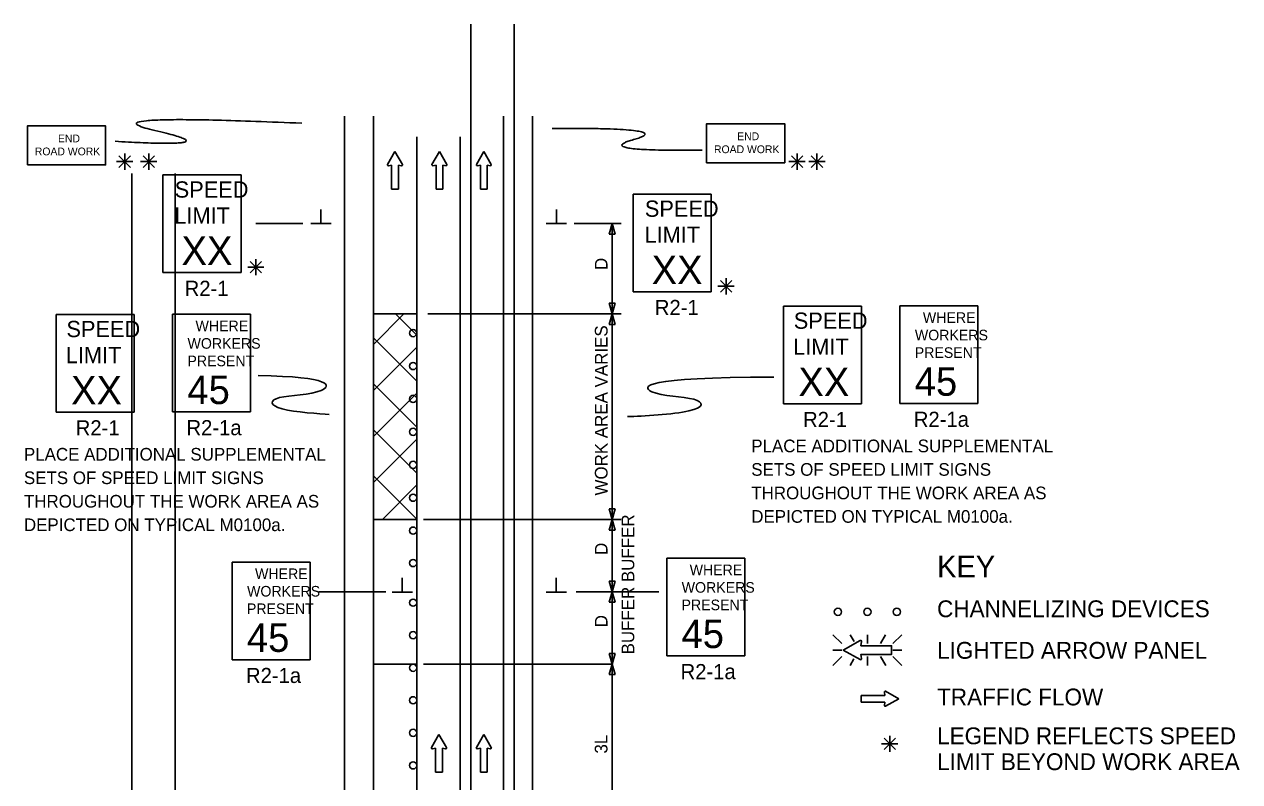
# Model space of a CAD drawing. Extents: x 16576 to 19504, y 5728 to 6974.
# Drawn here: x 16734 to 17406, y 6555 to 6974 of the extents above; entities that cross this region are included whole.
import ezdxf

# ---------------------------------------------------------------- set-up
doc = ezdxf.new("R2010")
doc.units = 0
for name, color, linetype in [('ALI_LEGAL_EX', 7, 'Continuous'), ('MT_SCRATCH_LEVEL_E', 7, 'Continuous'), ('PAVT_EDGE_EX', 7, 'Continuous'), ('TRAFFIC_SIGNS_PR', 7, 'Continuous'), ('TYPICAL_TEXT_DIMEN_EX', 7, 'Continuous'), ('TYPICAL_TEXT_DIMEN_PR', 7, 'Continuous')]:
    doc.layers.add(name, color=color, linetype=linetype)

msp = doc.modelspace()

# ---------------------------------------------------------------- linework, layer by layer
at = {"layer": 'ALI_LEGAL_EX'}
for p, q in [((16980.68, 6974.12), (16980.68, 6155.98)), ((17004.68, 6974.12), (17004.68, 6155.98)), ((16950.77, 6911.88), (16950.77, 6082.69)), ((16974.77, 6911.88), (16974.77, 6082.69)), ((16793.2, 6891.57), (16793.2, 6027.66)), ((16817.2, 6891.57), (16817.2, 6027.66))]:
    msp.add_line(p, q, dxfattribs=at)
for points in [[(17004.68, 6949.12), (17004.68, 6974.12)], [(16950.77, 6911.88), (16950.77, 6886.88)], [(16974.77, 6911.88), (16974.77, 6886.88)], [(16950.77, 6811.88), (16950.77, 6786.88)], [(16974.77, 6811.88), (16974.77, 6786.88)], [(16950.77, 6711.88), (16950.77, 6686.88)], [(16974.77, 6711.88), (16974.77, 6686.88)], [(16950.77, 6611.88), (16950.77, 6586.88)], [(16974.77, 6611.88), (16974.77, 6586.88)]]:
    msp.add_lwpolyline(points, dxfattribs=at)
at = {"layer": 'MT_SCRATCH_LEVEL_E'}
for p, q in [((16938.74, 6903.85), (16934.63, 6896.61)), ((16942.89, 6896.61), (16938.74, 6903.85)), ((16963.3, 6903.85), (16959.19, 6896.61)), ((16967.44, 6896.61), (16963.3, 6903.85)), ((16987.86, 6903.85), (16983.75, 6896.61)), ((16992, 6896.61), (16987.86, 6903.85)), ((16935.11, 6895.92), (16936.89, 6896.24)), ((16936.89, 6896.24), (16936.89, 6882.98)), ((16940.63, 6882.98), (16940.63, 6896.24)), ((16940.63, 6896.24), (16942.41, 6895.92)), ((16959.67, 6895.92), (16961.45, 6896.24)), ((16961.45, 6896.24), (16961.45, 6882.98)), ((16965.19, 6882.98), (16965.19, 6896.24)), ((16965.19, 6896.24), (16966.97, 6895.92)), ((16984.23, 6895.92), (16986.01, 6896.24)), ((16986.01, 6896.24), (16986.01, 6882.98)), ((16989.75, 6882.98), (16989.75, 6896.24)), ((16989.75, 6896.24), (16991.53, 6895.92)), ((16936.89, 6882.98), (16940.63, 6882.98)), ((16961.45, 6882.98), (16965.19, 6882.98)), ((16986.01, 6882.98), (16989.75, 6882.98)), ((17209.76, 6602.9), (17196.5, 6602.9)), ((17196.5, 6602.9), (17196.5, 6599.15)), ((17209.44, 6604.67), (17209.76, 6602.9)), ((17217.37, 6601.04), (17210.13, 6605.16)), ((17196.5, 6599.15), (17209.76, 6599.15)), ((17209.76, 6599.15), (17209.44, 6597.38)), ((17210.13, 6596.9), (17217.37, 6601.04)), ((16963.08, 6581.24), (16958.97, 6574)), ((16967.23, 6574), (16963.08, 6581.24)), ((16987.86, 6581.26), (16983.75, 6574.02)), ((16992, 6574.02), (16987.86, 6581.26)), ((16959.45, 6573.32), (16961.23, 6573.63)), ((16961.23, 6573.63), (16961.23, 6560.38)), ((16964.97, 6560.38), (16964.97, 6573.63)), ((16964.97, 6573.63), (16966.75, 6573.32)), ((16984.23, 6573.33), (16986.01, 6573.65)), ((16986.01, 6573.65), (16986.01, 6560.39)), ((16989.75, 6560.39), (16989.75, 6573.65)), ((16989.75, 6573.65), (16991.53, 6573.33)), ((16961.23, 6560.38), (16964.97, 6560.38)), ((16986.01, 6560.39), (16989.75, 6560.39))]:
    msp.add_line(p, q, dxfattribs=at)
for centre, start, end in [((16935.04, 6896.38), 150.42484, 279.96381), ((16942.48, 6896.38), 260.03619, 29.77312), ((16959.59, 6896.38), 150.42484, 279.96381), ((16967.04, 6896.38), 260.03619, 29.77312), ((16984.15, 6896.38), 150.42484, 279.96381), ((16991.59, 6896.38), 260.03619, 29.77312), ((17209.9, 6604.75), 60.42484, 189.96381), ((17209.9, 6597.31), 170.03619, 299.77312), ((16959.38, 6573.78), 150.42484, 279.96381), ((16966.82, 6573.78), 260.03619, 29.77312), ((16984.15, 6573.79), 150.42484, 279.96381), ((16991.59, 6573.79), 260.03619, 29.77312)]:
    msp.add_arc(centre, 0.463, start, end, dxfattribs=at)
at = {"layer": 'PAVT_EDGE_EX'}
for p, q in [((16910.77, 6923.28), (16910.77, 5986.88)), ((16926.77, 6923.28), (16926.77, 5986.88)), ((16998.77, 6923.28), (16998.77, 5986.88)), ((17014.77, 6923.28), (17014.77, 5986.88)), ((16926.77, 6813.97), (16950.77, 6813.97)), ((16926.77, 6797.07), (16943.67, 6813.97)), ((16950.86, 6813.97), (16926.86, 6813.97)), ((16950.77, 6802.15), (16938.96, 6813.97)), ((16950.77, 6776.7), (16926.77, 6800.7)), ((16926.77, 6771.61), (16950.77, 6795.61)), ((16950.77, 6751.24), (16926.77, 6775.24)), ((16926.77, 6746.16), (16950.77, 6770.16)), ((16950.77, 6725.79), (16926.77, 6749.79)), ((16926.77, 6720.7), (16950.77, 6744.7)), ((16950.77, 6700.33), (16926.77, 6724.33)), ((16931.77, 6700.24), (16950.86, 6719.34))]:
    msp.add_line(p, q, dxfattribs=at)
msp.add_lwpolyline([(16950.86, 6700.24), (16926.77, 6700.24), (16926.77, 6620.24), (16950.86, 6620.24)], close=True, dxfattribs=at)
at = {"layer": 'TRAFFIC_SIGNS_PR'}
for p, q in [((16810.4, 6890.77), (16853.6, 6890.77)), ((16810.4, 6836.77), (16810.4, 6890.77)), ((16853.6, 6836.77), (16853.6, 6890.77)), ((17070.45, 6880.17), (17113.65, 6880.17)), ((17070.45, 6826.17), (17070.45, 6880.17)), ((17113.65, 6826.17), (17113.65, 6880.17)), ((16810.4, 6836.77), (16853.6, 6836.77)), ((17070.45, 6826.17), (17113.65, 6826.17)), ((17153.65, 6818.22), (17196.85, 6818.22)), ((17153.65, 6764.22), (17153.65, 6818.22)), ((17196.85, 6764.22), (17196.85, 6818.22)), ((17218, 6818.32), (17261.2, 6818.32)), ((17218, 6764.32), (17218, 6818.32)), ((17261.2, 6764.32), (17261.2, 6818.32)), ((16751.34, 6813.6), (16794.54, 6813.6)), ((16751.34, 6759.6), (16751.34, 6813.6)), ((16794.54, 6759.6), (16794.54, 6813.6)), ((16815.69, 6813.7), (16858.89, 6813.7)), ((16815.69, 6759.7), (16815.69, 6813.7)), ((16858.89, 6759.7), (16858.89, 6813.7)), ((17153.65, 6764.22), (17196.85, 6764.22)), ((17218, 6764.32), (17261.2, 6764.32)), ((16751.34, 6759.6), (16794.54, 6759.6)), ((16815.69, 6759.7), (16858.89, 6759.7)), ((16848.61, 6676.62), (16891.81, 6676.62)), ((16848.61, 6622.62), (16848.61, 6676.62)), ((16891.81, 6622.62), (16891.81, 6676.62)), ((17089.01, 6678.74), (17132.21, 6678.74)), ((17089.01, 6624.74), (17089.01, 6678.74)), ((17132.21, 6624.74), (17132.21, 6678.74)), ((17180.95, 6636.47), (17185.88, 6631.54)), ((17192.71, 6632.65), (17190.51, 6636.47)), ((17200.03, 6631.54), (17200.03, 6636.47)), ((17207.27, 6631.54), (17210.12, 6636.47)), ((17214.18, 6631.54), (17219.12, 6636.48)), ((16848.61, 6622.62), (16891.81, 6622.62)), ((17089.01, 6624.74), (17132.21, 6624.74)), ((17185.88, 6627.98), (17180.95, 6627.98)), ((17180.95, 6619.5), (17185.88, 6624.43)), ((17190.46, 6619.49), (17192.57, 6623.16)), ((17200.03, 6624.43), (17200.03, 6619.49)), ((17210.16, 6619.49), (17207.31, 6624.43)), ((17214.18, 6627.98), (17219.12, 6627.98)), ((17214.18, 6624.43), (17219.12, 6619.49))]:
    msp.add_line(p, q, dxfattribs=at)
for points in [[(16735.46, 6896.3), (16778.66, 6896.3), (16778.66, 6917.9), (16735.46, 6917.9)], [(17111.13, 6897.5), (17154.33, 6897.5), (17154.33, 6919.1), (17111.13, 6919.1)]]:
    msp.add_lwpolyline(points, close=True, dxfattribs=at)
for points in [[(17195.96, 6633.26), (17186.67, 6627.98), (17195.96, 6622.66)], [(17196.84, 6623.29), (17196.44, 6625.56), (17213.45, 6625.56), (17213.45, 6630.36), (17196.44, 6630.36), (17196.84, 6632.64)]]:
    msp.add_lwpolyline(points, dxfattribs=at)
for centre in [(16948.76, 6803.32), (16948.76, 6785.1), (16948.76, 6766.89), (16948.76, 6748.67), (16948.76, 6730.46), (16948.76, 6712.25), (16948.76, 6694.03), (16948.76, 6676.13), (16948.76, 6654.19), (17183.74, 6649.1), (17200.04, 6649.1), (17216.34, 6649.1), (16948.76, 6636.19), (16948.76, 6618.19), (16948.76, 6600.19), (16948.76, 6582.19), (16948.76, 6564.19)]:
    msp.add_circle(centre, 2, dxfattribs=at)
for centre, radius, start, end in [((17196.25, 6632.74), 0.598, 350.73078, 118.89165), ((17196.25, 6623.19), 0.597, 241.48329, 9.95933)]:
    msp.add_arc(centre, radius, start, end, dxfattribs=at)
for points in [[(16783.94, 6909.41), (16849.1, 6905.54), (16764.08, 6924.88), (16887.17, 6919.39)], [(17108.72, 6904.51), (17046.96, 6903.75), (17094.87, 6917.06), (17025.7, 6916.51)]]:
    msp.add_open_spline(points, degree=2, dxfattribs=at)
at = {"layer": 'TYPICAL_TEXT_DIMEN_EX'}
for p, q in [((17212.44, 6576.11), (17207.91, 6576.11)), ((17209.25, 6579.3), (17215.63, 6572.93)), ((17215.63, 6579.3), (17209.25, 6572.93)), ((17212.44, 6576.11), (17212.44, 6580.57)), ((17212.44, 6576.11), (17215.63, 6576.11)), ((17212.44, 6576.11), (17216.92, 6576.11)), ((17212.44, 6576.11), (17212.44, 6571.61))]:
    msp.add_line(p, q, dxfattribs=at)
at = {"layer": 'TYPICAL_TEXT_DIMEN_PR'}
for p, q in [((16789.26, 6898.18), (16784.72, 6898.18)), ((16786.07, 6901.37), (16792.44, 6894.99)), ((16792.44, 6901.37), (16786.07, 6894.99)), ((16789.26, 6898.18), (16789.26, 6902.64)), ((16789.26, 6898.18), (16792.44, 6898.18)), ((16789.26, 6898.18), (16793.74, 6898.18)), ((16789.26, 6898.18), (16789.26, 6893.68)), ((16802.58, 6898.18), (16798.05, 6898.18)), ((16799.39, 6901.37), (16805.77, 6894.99)), ((16805.77, 6901.37), (16799.39, 6894.99)), ((16802.58, 6898.18), (16802.58, 6902.64)), ((16802.58, 6898.18), (16805.77, 6898.18)), ((16802.58, 6898.18), (16807.06, 6898.18)), ((16802.58, 6898.18), (16802.58, 6893.68)), ((17161.16, 6898.16), (17156.63, 6898.16)), ((17157.97, 6901.35), (17164.35, 6894.97)), ((17164.35, 6901.35), (17157.97, 6894.97)), ((17161.16, 6898.16), (17161.16, 6902.62)), ((17161.16, 6898.16), (17164.35, 6898.16)), ((17161.16, 6898.16), (17165.64, 6898.16)), ((17161.16, 6898.16), (17161.16, 6893.66)), ((17172.13, 6898.16), (17167.6, 6898.16)), ((17168.94, 6901.35), (17175.32, 6894.97)), ((17175.32, 6901.35), (17168.94, 6894.97)), ((17172.13, 6898.16), (17172.13, 6902.62)), ((17172.13, 6898.16), (17175.32, 6898.16)), ((17172.13, 6898.16), (17176.61, 6898.16)), ((17172.13, 6898.16), (17172.13, 6893.66)), ((16897.73, 6863.97), (16897.73, 6871.75)), ((17027.98, 6863.97), (17027.98, 6871.75)), ((16861.77, 6863.97), (16887.77, 6863.97)), ((16892.11, 6863.97), (16903.36, 6863.97)), ((17033.61, 6863.97), (17022.36, 6863.97)), ((17063.86, 6863.97), (17037.86, 6863.97)), ((17057.29, 6858.11), (17058.86, 6863.97)), ((17058.86, 6863.97), (17058.86, 6813.97)), ((17058.86, 6863.97), (17060.43, 6858.11)), ((17058.86, 6858.11), (17057.29, 6858.11)), ((17060.43, 6858.11), (17058.86, 6858.11)), ((16861.8, 6839.81), (16861.8, 6844.26)), ((16861.8, 6839.81), (16857.27, 6839.81)), ((16858.61, 6842.99), (16864.99, 6836.62)), ((16864.99, 6842.99), (16858.61, 6836.62)), ((16861.8, 6839.81), (16864.99, 6839.81)), ((16861.8, 6839.81), (16866.28, 6839.81)), ((16861.8, 6839.81), (16861.8, 6835.31)), ((17058.86, 6838.84), (17058.86, 6835.07)), ((17118.72, 6832.39), (17125.09, 6826.01)), ((17125.09, 6832.39), (17118.72, 6826.01)), ((17121.9, 6829.2), (17121.9, 6833.66)), ((17121.9, 6829.2), (17117.37, 6829.2)), ((17121.9, 6829.2), (17125.09, 6829.2)), ((17121.9, 6829.2), (17126.38, 6829.2)), ((17121.9, 6829.2), (17121.9, 6824.7)), ((17058.86, 6813.97), (17057.29, 6819.83)), ((17057.29, 6819.83), (17058.86, 6819.83)), ((17058.86, 6819.83), (17060.43, 6819.83)), ((17060.43, 6819.83), (17058.86, 6813.97)), ((17063.86, 6813.97), (16956.85, 6813.97)), ((17057.29, 6808.11), (17058.86, 6813.97)), ((17058.86, 6700.24), (17058.86, 6813.97)), ((17058.86, 6813.97), (17060.43, 6808.11)), ((17058.86, 6808.11), (17057.29, 6808.11)), ((17060.43, 6808.11), (17058.86, 6808.11)), ((17058.86, 6700.24), (17057.29, 6706.11)), ((17057.29, 6706.11), (17058.86, 6706.11)), ((17058.86, 6706.11), (17060.43, 6706.11)), ((17060.43, 6706.11), (17058.86, 6700.24)), ((17063.86, 6700.24), (16954.58, 6700.24)), ((17057.29, 6694.38), (17058.86, 6700.24)), ((17058.86, 6660.24), (17058.86, 6700.24)), ((17058.86, 6700.24), (17060.43, 6694.38)), ((17058.86, 6694.38), (17057.29, 6694.38)), ((17060.43, 6694.38), (17058.86, 6694.38)), ((16942.72, 6660.09), (16942.72, 6667.87)), ((17027.9, 6660.09), (17027.9, 6667.87)), ((17058.86, 6660.24), (17057.29, 6666.11)), ((17057.29, 6666.11), (17058.86, 6666.11)), ((17058.86, 6666.11), (17060.43, 6666.11)), ((17060.43, 6666.11), (17058.86, 6660.24)), ((16933.65, 6660.24), (16896.53, 6660.24)), ((16948.34, 6660.09), (16937.09, 6660.09)), ((17033.52, 6660.09), (17022.27, 6660.09)), ((17084.64, 6660.24), (17038.93, 6660.24)), ((17057.29, 6654.38), (17058.86, 6660.24)), ((17058.86, 6620.24), (17058.86, 6660.24)), ((17058.86, 6660.24), (17060.43, 6654.38)), ((17058.86, 6654.38), (17057.29, 6654.38)), ((17060.43, 6654.38), (17058.86, 6654.38)), ((17058.86, 6620.24), (17057.29, 6626.11)), ((17057.29, 6626.11), (17058.86, 6626.11)), ((17058.86, 6626.11), (17060.43, 6626.11)), ((17060.43, 6626.11), (17058.86, 6620.24)), ((17058.86, 6620.24), (16954.58, 6620.24)), ((17057.29, 6614.38), (17058.86, 6620.24)), ((17058.86, 6620.24), (17058.77, 6528.19)), ((17058.86, 6620.24), (17060.43, 6614.38)), ((17058.86, 6614.38), (17057.29, 6614.38)), ((17060.43, 6614.38), (17058.86, 6614.38))]:
    msp.add_line(p, q, dxfattribs=at)
for points in [[(16863.02, 6779.76), (16904.09, 6779.23), (16903.49, 6769.05), (16869.19, 6769.05), (16869.19, 6760.47), (16897.45, 6758.59), (16902.37, 6758.34)], [(17148.3, 6778.96), (17074.92, 6778.96), (17074.92, 6768.21), (17109.84, 6768.21), (17109.84, 6759.16), (17075.63, 6757.39), (17067.34, 6757.11)]]:
    msp.add_open_spline(points, degree=3, dxfattribs=at)

# ---------------------------------------------------------------- texts
at = {"layer": 'TRAFFIC_SIGNS_PR'}
for s, height, p in [('END', 4.31, (16752.34, 6908.82)), ('END', 4.31, (17128.01, 6910.02)), ('ROAD WORK', 4.31, (16739.52, 6901.63)), ('ROAD WORK', 4.31, (17115.19, 6902.84)), ('SPEED', 9, (16816.89, 6878.24)), ('LIMIT', 9, (16816.7, 6863.84)), ('SPEED', 9, (17076.94, 6867.64)), ('LIMIT', 9, (17076.75, 6853.24)), ('XX', 15.785, (16820.65, 6841)), ('XX', 15.785, (17080.7, 6830.39)), ('R2-1', 8.37, (16822.41, 6823.9)), ('R2-1', 8.37, (17082.46, 6813.3)), ('SPEED', 9, (16757, 6801.07)), ('WHERE', 5.85, (16828.41, 6804.34)), ('SPEED', 9, (17159.31, 6805.69)), ('WHERE', 5.85, (17230.72, 6808.96)), ('WORKERS', 5.85, (17226.3, 6799.29)), ('WORKERS', 5.85, (16823.99, 6794.67)), ('LIMIT', 9, (17158.94, 6791.29)), ('LIMIT', 9, (16756.63, 6786.67)), ('PRESENT', 5.85, (16823.92, 6784.99)), ('PRESENT', 5.85, (17226.23, 6789.61)), ('XX', 15.785, (17161.87, 6768.44)), ('45', 15.785, (17226.22, 6768.65)), ('XX', 15.785, (16759.56, 6763.83)), ('45', 15.785, (16823.91, 6764.04)), ('R2-1', 8.37, (17164.46, 6751.35)), ('R2-1a', 8.37, (17225.71, 6751.45)), ('R2-1', 8.37, (16762.15, 6746.73)), ('R2-1a', 8.37, (16823.4, 6746.83)), ('PLACE ADDITIONAL SUPPLEMENTAL', 7, (17135.8, 6737.39)), ('PLACE ADDITIONAL SUPPLEMENTAL', 7, (16733.5, 6732.78)), ('SETS OF SPEED LIMIT SIGNS', 7, (17135.8, 6724.39)), ('SETS OF SPEED LIMIT SIGNS', 7, (16733.5, 6719.78)), ('THROUGHOUT THE WORK AREA AS', 7, (17135.8, 6711.39)), ('THROUGHOUT THE WORK AREA AS', 7, (16733.5, 6706.78)), ('DEPICTED ON TYPICAL M0100a.', 7, (17135.8, 6698.39)), ('DEPICTED ON TYPICAL M0100a.', 7, (16733.5, 6693.78)), ('WHERE', 5.85, (16861.34, 6667.26)), ('WHERE', 5.85, (17101.73, 6669.38)), ('WORKERS', 5.85, (16856.92, 6657.59)), ('WORKERS', 5.85, (17097.31, 6659.71)), ('PRESENT', 5.85, (17097.24, 6650.03)), ('PRESENT', 5.85, (16856.84, 6647.91)), ('45', 15.785, (16856.83, 6626.96)), ('45', 15.785, (17097.23, 6629.08)), ('R2-1a', 8.37, (16856.32, 6609.75)), ('R2-1a', 8.37, (17096.72, 6611.87))]:
    msp.add_text(s, height=height, dxfattribs=at).set_placement(p)
at = {"layer": 'TYPICAL_TEXT_DIMEN_EX'}
for s, height, p in [('KEY', 12, (17238.58, 6668.2)), ('CHANNELIZING DEVICES', 9.31, (17238.58, 6646.15)), ('LIGHTED ARROW PANEL', 9.31, (17238.58, 6623.16)), ('TRAFFIC FLOW', 9.3, (17238.58, 6597.36)), ('LEGEND REFLECTS SPEED', 9.31, (17238.58, 6575.87)), ('LIMIT BEYOND WORK AREA', 9.31, (17238.58, 6561.56))]:
    msp.add_text(s, height=height, dxfattribs=at).set_placement(p)
at = {"layer": 'TYPICAL_TEXT_DIMEN_PR'}
for s, p in [('D', (17056.3, 6838.19)), ('WORK AREA VARIES', (17056.3, 6713.46)), ('BUFFER', (17071.09, 6665.57)), ('D', (17056.3, 6680.59)), ('BUFFER', (17071.09, 6625.57)), ('D', (17056.3, 6640.59)), ('3L', (17056.26, 6570.72))]:
    msp.add_text(s, height=7, rotation=90, dxfattribs=at).set_placement(p)

doc.saveas('drawing.dxf')
